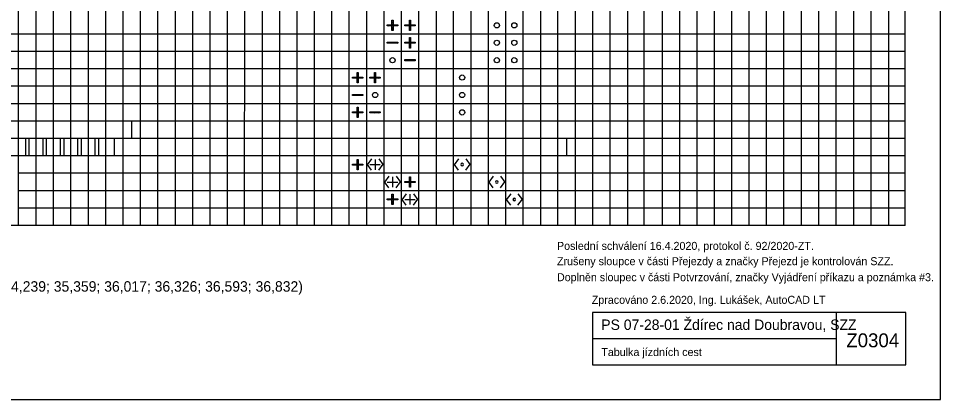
# Model space of a CAD drawing. Extents: x 2343 to 5155, y -3940 to 2050.
# Drawn here: x 4705 to 4970, y -3940 to -3830.5 of the extents above; entities that cross this region are included whole.
import ezdxf

# ---------------------------------------------------------------- set-up
doc = ezdxf.new("R2010")
doc.units = 0
for name, color, linetype in [('0B', 7, 'Continuous'), ('Implicitní', 7, 'Continuous'), ('Vrstva 1', 7, 'Continuous'), ('Vrstva 63', 7, 'Continuous')]:
    doc.layers.add(name, color=color, linetype=linetype)

# ---------------------------------------------------------------- blocks, each defined once
blk = doc.blocks.new('ZT82')
at = {"layer": 'Implicitní'}
for points in [[(25, 40), (25, 10)], [(10, 25), (40, 25)]]:
    blk.add_lwpolyline(points, dxfattribs=at)
blk = doc.blocks.new('ZT175')
at = {"layer": 'Vrstva 1'}
blk.add_circle((0, 0), 0.75, dxfattribs=at)
blk = doc.blocks.new('ZN8')
at = {"layer": 'Implicitní'}
for start, end in [(0, 180), (180, 0)]:
    blk.add_arc((0, 0), 3.75, start, end, dxfattribs=at)

msp = doc.modelspace()

# ---------------------------------------------------------------- linework, layer by layer
for p, q in [((4710, -3667.5), (4710, -3890)), ((4715, -3667.5), (4715, -3890)), ((4720, -3667.5), (4720, -3890)), ((4725, -3667.5), (4725, -3890)), ((4730, -3667.5), (4730, -3890)), ((4735, -3667.5), (4735, -3890)), ((4740, -3667.5), (4740, -3890)), ((4745, -3667.5), (4745, -3890)), ((4750, -3667.5), (4750, -3890)), ((4755, -3667.5), (4755, -3890)), ((4760, -3667.5), (4760, -3890)), ((4765, -3667.5), (4765, -3890)), ((4770, -3667.5), (4769.91, -3890)), ((4775, -3667.5), (4775, -3890)), ((4780, -3667.5), (4780, -3890)), ((4785, -3667.5), (4785, -3890)), ((4790, -3667.5), (4790, -3890)), ((4795, -3667.5), (4795, -3890)), ((4805, -3667.5), (4805, -3890)), ((4810, -3667.5), (4810, -3890)), ((4815, -3667.5), (4815, -3890)), ((4820, -3667.5), (4820, -3890)), ((4825, -3667.5), (4825, -3890)), ((4835, -3667.5), (4835, -3890)), ((4840, -3667.5), (4840, -3890)), ((4845, -3667.5), (4845, -3890)), ((4850, -3667.5), (4850, -3890)), ((4855, -3667.5), (4855, -3890)), ((4865, -3667.5), (4865, -3890)), ((4870, -3667.5), (4870, -3890)), ((4875, -3667.5), (4875, -3890)), ((4880, -3667.5), (4880, -3890)), ((4890, -3667.5), (4890, -3890)), ((4895, -3667.5), (4895, -3890)), ((4900, -3667.5), (4900, -3890)), ((4905, -3890), (4905, -3667.5)), ((4915, -3890), (4915, -3667.5)), ((4920, -3890), (4920, -3667.5)), ((4925, -3890), (4925, -3667.5)), ((4930, -3890), (4930, -3667.5)), ((4935, -3890), (4935, -3667.5)), ((4945, -3667.5), (4945, -3890)), ((4950, -3667.5), (4950, -3890)), ((4955, -3667.5), (4955, -3890)), ((4959.82, -3835), (4705, -3835)), ((4959.82, -3840), (4705, -3840)), ((4959.82, -3840), (4705, -3840)), ((4959.82, -3845), (4705, -3845)), ((4959.82, -3845), (4705, -3845)), ((4959.82, -3845), (4705, -3845)), ((4959.82, -3850), (4705, -3850)), ((4959.82, -3855), (4705, -3855)), ((4959.82, -3860), (4705, -3860)), ((4959.82, -3860), (4705, -3860)), ((4959.82, -3865), (4705, -3865)), ((4959.82, -3870), (4705, -3870)), ((4959.82, -3875), (4705, -3875)), ((4959.82, -3875), (4705, -3875)), ((4959.82, -3880), (4705, -3880)), ((4959.82, -3880), (4705, -3880)), ((4959.82, -3885), (4705, -3885))]:
    msp.add_line(p, q)
for points in [[(4959.82, -3840), (4705, -3840)], [(4959.82, -3845), (4705, -3845)], [(4737.5, -3860.02), (4737.5, -3865.02)], [(4707, -3865.02), (4707, -3870.02)], [(4708, -3865.02), (4708, -3870.02)], [(4712, -3865.02), (4712, -3870.02)], [(4713, -3865.02), (4713, -3870.02)], [(4717, -3865.02), (4717, -3870.02)], [(4718, -3865.02), (4718, -3870.02)], [(4722, -3865.02), (4722, -3870.02)], [(4723, -3865.02), (4723, -3870.02)], [(4727, -3865.02), (4727, -3870.02)], [(4728, -3865.02), (4728, -3870.02)], [(4732.5, -3865.02), (4732.5, -3870.02)], [(4862.5, -3865.02), (4862.5, -3870.02)], [(4959.82, -3875), (4705, -3875)]]:
    msp.add_lwpolyline(points)
at = {"layer": '0B'}
for p, q in [((4705, -3835), (4585, -3835)), ((4705, -3840), (4585, -3840)), ((4705, -3840), (4585, -3840)), ((4705, -3840), (4585, -3840)), ((4705, -3845), (4585, -3845)), ((4705, -3845), (4585, -3845)), ((4705, -3845), (4585, -3845)), ((4705, -3845), (4585, -3845)), ((4705, -3850), (4585, -3850)), ((4705, -3855), (4585, -3855)), ((4705, -3860), (4585, -3860)), ((4705, -3860), (4585, -3860)), ((4705, -3865), (4585, -3865)), ((4705, -3870), (4585, -3870)), ((4960, -3915), (4870, -3915)), ((4870, -3915), (4870, -3930)), ((4940, -3915), (4940, -3930)), ((4960, -3930), (4960, -3915)), ((4870, -3922.5), (4940, -3922.5)), ((4870, -3930), (4960, -3930))]:
    msp.add_line(p, q, dxfattribs=at)
for points in [[(4705, -3890), (4705, -3660)], [(4800, -3890), (4800, -3660)], [(4830, -3890), (4830, -3660)], [(4860, -3890), (4860, -3660)], [(4884.82, -3890), (4884.82, -3660)], [(4910, -3890), (4910, -3660)], [(4940, -3890), (4940, -3660)], [(4959.82, -3890), (4959.82, -3660)], [(4806.47, -3870.86), (4805.19, -3872.59)], [(4808.53, -3870.86), (4809.81, -3872.59)], [(4831.47, -3870.86), (4830.19, -3872.59)], [(4833.53, -3870.86), (4834.81, -3872.59)], [(4806.47, -3874.14), (4805.19, -3872.41)], [(4808.53, -3874.14), (4809.81, -3872.41)], [(4831.47, -3874.14), (4830.19, -3872.41)], [(4833.53, -3874.14), (4834.81, -3872.41)], [(4811.47, -3875.86), (4810.19, -3877.59)], [(4813.53, -3875.86), (4814.81, -3877.59)], [(4841.47, -3875.86), (4840.19, -3877.59)], [(4843.53, -3875.86), (4844.81, -3877.59)], [(4811.47, -3879.14), (4810.19, -3877.41)], [(4813.53, -3879.14), (4814.81, -3877.41)], [(4841.47, -3879.14), (4840.19, -3877.41)], [(4843.53, -3879.14), (4844.81, -3877.41)], [(4816.47, -3880.86), (4815.19, -3882.59)], [(4818.53, -3880.86), (4819.81, -3882.59)], [(4846.47, -3880.86), (4845.19, -3882.59)], [(4848.53, -3880.86), (4849.81, -3882.59)], [(4816.47, -3884.14), (4815.19, -3882.41)], [(4818.53, -3884.14), (4819.81, -3882.41)], [(4846.47, -3884.14), (4845.19, -3882.41)], [(4848.53, -3884.14), (4849.81, -3882.41)], [(4959.82, -3890), (4580, -3890)]]:
    msp.add_lwpolyline(points, dxfattribs=at)
at = {"layer": 'Vrstva 1'}
for p, q in [((4812.35, -3831.16), (4812.51, -3831)), ((4812.35, -3832.35), (4812.35, -3831)), ((4812.35, -3831), (4812.65, -3831)), ((4812.35, -3831.69), (4812.65, -3831.39)), ((4812.65, -3831), (4812.65, -3832.35)), ((4817.35, -3831.16), (4817.51, -3831)), ((4817.35, -3832.35), (4817.35, -3831)), ((4817.35, -3831), (4817.65, -3831)), ((4817.35, -3831.69), (4817.65, -3831.39)), ((4817.65, -3831), (4817.65, -3832.35)), ((4811, -3832.51), (4811.16, -3832.35)), ((4811, -3832.35), (4812.35, -3832.35)), ((4811, -3832.65), (4811, -3832.35)), ((4812.35, -3832.65), (4811, -3832.65)), ((4811.39, -3832.65), (4811.69, -3832.35)), ((4811.92, -3832.65), (4812.22, -3832.35)), ((4812.35, -3832.22), (4812.65, -3831.92)), ((4812.35, -3832.75), (4812.75, -3832.35)), ((4812.35, -3834), (4812.35, -3832.65)), ((4812.35, -3833.28), (4812.65, -3832.98)), ((4812.35, -3833.81), (4812.65, -3833.51)), ((4812.65, -3834), (4812.35, -3834)), ((4812.65, -3832.35), (4814, -3832.35)), ((4814, -3832.65), (4812.65, -3832.65)), ((4812.65, -3832.65), (4812.65, -3834)), ((4812.98, -3832.65), (4813.28, -3832.35)), ((4813.51, -3832.65), (4813.81, -3832.35)), ((4814, -3832.35), (4814, -3832.65)), ((4816, -3832.51), (4816.16, -3832.35)), ((4816, -3832.35), (4817.35, -3832.35)), ((4816, -3832.65), (4816, -3832.35)), ((4817.35, -3832.65), (4816, -3832.65)), ((4816.39, -3832.65), (4816.69, -3832.35)), ((4816.92, -3832.65), (4817.22, -3832.35)), ((4817.35, -3832.22), (4817.65, -3831.92)), ((4817.35, -3832.75), (4817.75, -3832.35)), ((4817.35, -3834), (4817.35, -3832.65)), ((4817.35, -3833.28), (4817.65, -3832.98)), ((4817.35, -3833.81), (4817.65, -3833.51)), ((4817.65, -3834), (4817.35, -3834)), ((4817.65, -3832.35), (4819, -3832.35)), ((4819, -3832.65), (4817.65, -3832.65)), ((4817.65, -3832.65), (4817.65, -3834)), ((4817.98, -3832.65), (4818.28, -3832.35)), ((4818.51, -3832.65), (4818.81, -3832.35)), ((4819, -3832.35), (4819, -3832.65)), ((4817.35, -3836.16), (4817.51, -3836)), ((4817.35, -3837.35), (4817.35, -3836)), ((4817.35, -3836), (4817.65, -3836)), ((4817.35, -3836.69), (4817.65, -3836.39)), ((4817.35, -3837.22), (4817.65, -3836.92)), ((4817.65, -3836), (4817.65, -3837.35)), ((4811, -3837.35), (4814, -3837.35)), ((4811, -3837.65), (4811, -3837.35)), ((4814, -3837.65), (4811, -3837.65)), ((4811.21, -3837.65), (4811.51, -3837.35)), ((4811.74, -3837.65), (4812.04, -3837.35)), ((4812.27, -3837.65), (4812.57, -3837.35)), ((4812.8, -3837.65), (4813.1, -3837.35)), ((4813.33, -3837.65), (4813.63, -3837.35)), ((4813.86, -3837.65), (4814, -3837.51)), ((4814, -3837.35), (4814, -3837.65)), ((4816, -3837.51), (4816.16, -3837.35)), ((4816, -3837.35), (4817.35, -3837.35)), ((4816, -3837.65), (4816, -3837.35)), ((4817.35, -3837.65), (4816, -3837.65)), ((4816.39, -3837.65), (4816.69, -3837.35)), ((4816.92, -3837.65), (4817.22, -3837.35)), ((4817.35, -3837.75), (4817.75, -3837.35)), ((4817.35, -3839), (4817.35, -3837.65)), ((4817.35, -3838.28), (4817.65, -3837.98)), ((4817.35, -3838.81), (4817.65, -3838.51)), ((4817.65, -3839), (4817.35, -3839)), ((4817.65, -3837.35), (4819, -3837.35)), ((4819, -3837.65), (4817.65, -3837.65)), ((4817.65, -3837.65), (4817.65, -3839)), ((4817.98, -3837.65), (4818.28, -3837.35)), ((4818.51, -3837.65), (4818.81, -3837.35)), ((4819, -3837.35), (4819, -3837.65)), ((4816, -3842.35), (4819, -3842.35)), ((4816, -3842.65), (4816, -3842.35)), ((4816.21, -3842.65), (4816.51, -3842.35)), ((4816.74, -3842.65), (4817.04, -3842.35)), ((4817.27, -3842.65), (4817.57, -3842.35)), ((4817.8, -3842.65), (4818.1, -3842.35)), ((4818.33, -3842.65), (4818.63, -3842.35)), ((4819, -3842.35), (4819, -3842.65)), ((4819, -3842.65), (4816, -3842.65)), ((4818.86, -3842.65), (4819, -3842.51)), ((4801, -3847.51), (4801.16, -3847.35)), ((4801, -3847.35), (4802.35, -3847.35)), ((4801, -3847.65), (4801, -3847.35)), ((4802.35, -3847.65), (4801, -3847.65)), ((4801.39, -3847.65), (4801.69, -3847.35)), ((4801.92, -3847.65), (4802.22, -3847.35)), ((4802.35, -3846.16), (4802.51, -3846)), ((4802.35, -3847.35), (4802.35, -3846)), ((4802.35, -3846), (4802.65, -3846)), ((4802.35, -3846.69), (4802.65, -3846.39)), ((4802.35, -3847.22), (4802.65, -3846.92)), ((4802.35, -3847.75), (4802.75, -3847.35)), ((4802.35, -3849), (4802.35, -3847.65)), ((4802.65, -3846), (4802.65, -3847.35)), ((4802.65, -3847.35), (4804, -3847.35)), ((4804, -3847.65), (4802.65, -3847.65)), ((4802.65, -3847.65), (4802.65, -3849)), ((4802.98, -3847.65), (4803.28, -3847.35)), ((4803.51, -3847.65), (4803.81, -3847.35)), ((4804, -3847.35), (4804, -3847.65)), ((4806, -3847.51), (4806.16, -3847.35)), ((4806, -3847.35), (4807.35, -3847.35)), ((4806, -3847.65), (4806, -3847.35)), ((4807.35, -3847.65), (4806, -3847.65)), ((4806.39, -3847.65), (4806.69, -3847.35)), ((4806.92, -3847.65), (4807.22, -3847.35)), ((4807.35, -3846.16), (4807.51, -3846)), ((4807.35, -3847.35), (4807.35, -3846)), ((4807.35, -3846), (4807.65, -3846)), ((4807.35, -3846.69), (4807.65, -3846.39)), ((4807.35, -3847.22), (4807.65, -3846.92)), ((4807.35, -3847.75), (4807.75, -3847.35)), ((4807.35, -3849), (4807.35, -3847.65)), ((4807.65, -3846), (4807.65, -3847.35)), ((4807.65, -3847.35), (4809, -3847.35)), ((4809, -3847.65), (4807.65, -3847.65)), ((4807.65, -3847.65), (4807.65, -3849)), ((4807.98, -3847.65), (4808.28, -3847.35)), ((4808.51, -3847.65), (4808.81, -3847.35)), ((4809, -3847.35), (4809, -3847.65)), ((4802.35, -3848.28), (4802.65, -3847.98)), ((4802.35, -3848.81), (4802.65, -3848.51)), ((4802.65, -3849), (4802.35, -3849)), ((4807.35, -3848.28), (4807.65, -3847.98)), ((4807.35, -3848.81), (4807.65, -3848.51)), ((4807.65, -3849), (4807.35, -3849)), ((4801, -3852.35), (4804, -3852.35)), ((4801, -3852.65), (4801, -3852.35)), ((4804, -3852.65), (4801, -3852.65)), ((4801.21, -3852.65), (4801.51, -3852.35)), ((4801.74, -3852.65), (4802.04, -3852.35)), ((4802.27, -3852.65), (4802.57, -3852.35)), ((4802.8, -3852.65), (4803.1, -3852.35)), ((4803.33, -3852.65), (4803.63, -3852.35)), ((4803.86, -3852.65), (4804, -3852.51)), ((4804, -3852.35), (4804, -3852.65)), ((4801, -3857.51), (4801.16, -3857.35)), ((4801, -3857.35), (4802.35, -3857.35)), ((4801, -3857.65), (4801, -3857.35)), ((4802.35, -3857.65), (4801, -3857.65)), ((4801.39, -3857.65), (4801.69, -3857.35)), ((4801.92, -3857.65), (4802.22, -3857.35)), ((4802.35, -3856.16), (4802.51, -3856)), ((4802.35, -3857.35), (4802.35, -3856)), ((4802.35, -3856), (4802.65, -3856)), ((4802.35, -3856.69), (4802.65, -3856.39)), ((4802.35, -3857.22), (4802.65, -3856.92)), ((4802.35, -3857.75), (4802.75, -3857.35)), ((4802.35, -3859), (4802.35, -3857.65)), ((4802.35, -3858.28), (4802.65, -3857.98)), ((4802.65, -3856), (4802.65, -3857.35)), ((4802.65, -3857.35), (4804, -3857.35)), ((4804, -3857.65), (4802.65, -3857.65)), ((4802.65, -3857.65), (4802.65, -3859)), ((4802.98, -3857.65), (4803.28, -3857.35)), ((4803.51, -3857.65), (4803.81, -3857.35)), ((4804, -3857.35), (4804, -3857.65)), ((4806, -3857.35), (4809, -3857.35)), ((4806, -3857.65), (4806, -3857.35)), ((4809, -3857.65), (4806, -3857.65)), ((4806.21, -3857.65), (4806.51, -3857.35)), ((4806.74, -3857.65), (4807.04, -3857.35)), ((4807.27, -3857.65), (4807.57, -3857.35)), ((4807.8, -3857.65), (4808.1, -3857.35)), ((4808.33, -3857.65), (4808.63, -3857.35)), ((4808.86, -3857.65), (4809, -3857.51)), ((4809, -3857.35), (4809, -3857.65)), ((4802.35, -3858.81), (4802.65, -3858.51)), ((4802.65, -3859), (4802.35, -3859)), ((4802.35, -3871.16), (4802.51, -3871)), ((4802.35, -3872.35), (4802.35, -3871)), ((4802.35, -3871), (4802.65, -3871)), ((4802.35, -3871.69), (4802.65, -3871.39)), ((4802.65, -3871), (4802.65, -3872.35)), ((4801, -3872.51), (4801.16, -3872.35)), ((4801, -3872.35), (4802.35, -3872.35)), ((4801, -3872.65), (4801, -3872.35)), ((4802.35, -3872.65), (4801, -3872.65)), ((4801.39, -3872.65), (4801.69, -3872.35)), ((4801.92, -3872.65), (4802.22, -3872.35)), ((4802.35, -3872.22), (4802.65, -3871.92)), ((4802.35, -3872.75), (4802.75, -3872.35)), ((4802.35, -3874), (4802.35, -3872.65)), ((4802.35, -3873.28), (4802.65, -3872.98)), ((4802.35, -3873.81), (4802.65, -3873.51)), ((4802.65, -3874), (4802.35, -3874)), ((4802.65, -3872.35), (4804, -3872.35)), ((4804, -3872.65), (4802.65, -3872.65)), ((4802.65, -3872.65), (4802.65, -3874)), ((4802.98, -3872.65), (4803.28, -3872.35)), ((4803.51, -3872.65), (4803.81, -3872.35)), ((4804, -3872.35), (4804, -3872.65)), ((4817.35, -3876.16), (4817.51, -3876)), ((4817.35, -3877.35), (4817.35, -3876)), ((4817.35, -3876), (4817.65, -3876)), ((4817.35, -3876.69), (4817.65, -3876.39)), ((4817.35, -3877.22), (4817.65, -3876.92)), ((4817.65, -3876), (4817.65, -3877.35)), ((4816, -3877.51), (4816.16, -3877.35)), ((4816, -3877.35), (4817.35, -3877.35)), ((4816, -3877.65), (4816, -3877.35)), ((4817.35, -3877.65), (4816, -3877.65)), ((4816.39, -3877.65), (4816.69, -3877.35)), ((4816.92, -3877.65), (4817.22, -3877.35)), ((4817.35, -3877.75), (4817.75, -3877.35)), ((4817.35, -3879), (4817.35, -3877.65)), ((4817.35, -3878.28), (4817.65, -3877.98)), ((4817.35, -3878.81), (4817.65, -3878.51)), ((4817.65, -3879), (4817.35, -3879)), ((4817.65, -3877.35), (4819, -3877.35)), ((4819, -3877.65), (4817.65, -3877.65)), ((4817.65, -3877.65), (4817.65, -3879)), ((4817.98, -3877.65), (4818.28, -3877.35)), ((4818.51, -3877.65), (4818.81, -3877.35)), ((4819, -3877.35), (4819, -3877.65)), ((4812.35, -3881.16), (4812.51, -3881)), ((4812.35, -3882.35), (4812.35, -3881)), ((4812.35, -3881), (4812.65, -3881)), ((4812.35, -3881.69), (4812.65, -3881.39)), ((4812.35, -3882.22), (4812.65, -3881.92)), ((4812.65, -3881), (4812.65, -3882.35)), ((4811, -3882.51), (4811.16, -3882.35)), ((4811, -3882.35), (4812.35, -3882.35)), ((4811, -3882.65), (4811, -3882.35)), ((4812.35, -3882.65), (4811, -3882.65)), ((4811.39, -3882.65), (4811.69, -3882.35)), ((4811.92, -3882.65), (4812.22, -3882.35)), ((4812.35, -3882.75), (4812.75, -3882.35)), ((4812.35, -3884), (4812.35, -3882.65)), ((4812.35, -3883.28), (4812.65, -3882.98)), ((4812.35, -3883.81), (4812.65, -3883.51)), ((4812.65, -3884), (4812.35, -3884)), ((4812.65, -3882.35), (4814, -3882.35)), ((4814, -3882.65), (4812.65, -3882.65)), ((4812.65, -3882.65), (4812.65, -3884)), ((4812.98, -3882.65), (4813.28, -3882.35)), ((4813.51, -3882.65), (4813.81, -3882.35)), ((4814, -3882.35), (4814, -3882.65))]:
    msp.add_line(p, q, dxfattribs=at)
at = {"layer": 'Vrstva 63'}
msp.add_lwpolyline([(4550, -3940), (4970, -3940), (4970, -3643), (4550, -3643)], close=True, dxfattribs=at)

# ---------------------------------------------------------------- block references
for p in [(4842.5, -3832.5), (4847.5, -3832.5), (4842.5, -3837.5), (4847.5, -3837.5), (4812.5, -3842.5), (4842.5, -3842.5), (4847.5, -3842.5), (4832.5, -3847.5), (4807.5, -3852.5), (4832.5, -3852.5), (4832.5, -3857.5)]:
    msp.add_blockref('ZT175', p)
at = {"layer": '0B', "xscale": 0.1, "yscale": 0.10000000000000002, "rotation": -1.2050326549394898e-10}
for name, p in [('ZT82', (4805, -3875)), ('ZN8', (4832.5, -3872.5)), ('ZT82', (4810, -3880)), ('ZN8', (4842.5, -3877.5)), ('ZT82', (4815, -3885)), ('ZN8', (4847.5, -3882.5))]:
    msp.add_blockref(name, p, dxfattribs=at)

# ---------------------------------------------------------------- texts
at = {"layer": '0B'}
for s, height, p in [('Poslední schválení 16.4.2020, protokol č. 92/2020-ZT.', 2.2988, (4859.77, -3897)), ('Zrušeny sloupce v části Přejezdy a značky Přejezd je kontrolován SZZ.', 2.2988, (4859.77, -3901.4)), ('#3 Zajištění podmínek pro odjezd (PZS km 31,740; 33,183; 33,625; 34,239; 35,359; 36,017; 36,326; 36,593; 36,832)', 3, (4580, -3909)), ('Doplněn sloupec v části Potvrzování, značky Vyjádření příkazu a poznámka #3. ', 2.2988, (4859.77, -3906)), ('Zpracováno 2.6.2020, Ing. Lukášek, AutoCAD LT', 2.2988, (4869.77, -3912.5)), ('PS 07-28-01 Ždírec nad Doubravou, SZZ', 3, (4872.5, -3920)), ('Z0304', 4, (4942.92, -3924.98)), ('Tabulka jízdních cest', 2.3, (4872.5, -3927.5))]:
    msp.add_text(s, height=height, rotation=360, dxfattribs=at).set_placement(p)

doc.saveas('drawing.dxf')
